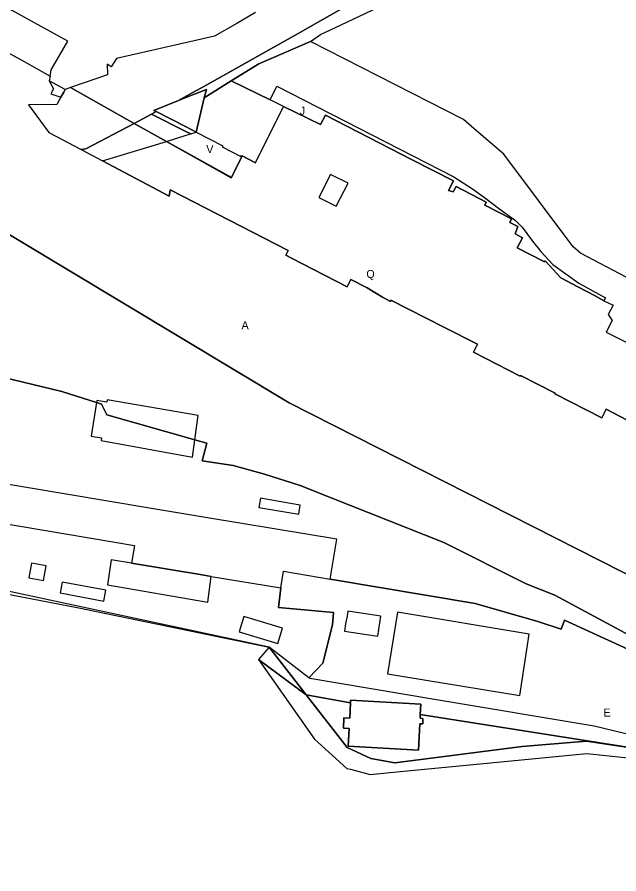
# Model space of a CAD drawing. Extents: x -749314 to -746497, y -1026537 to -1024935.
# Drawn here: x -748241.9 to -748054, y -1025476.4 to -1025208.8 of the extents above; entities that cross this region are included whole.
import ezdxf

# ---------------------------------------------------------------- set-up
doc = ezdxf.new("R2010")
doc.units = 0
for name, color, linetype in [('Default', 7, 'Continuous'), ('K_CD1', 7, 'Continuous'), ('K_DOSZDC1', 7, 'Continuous'), ('K_DOSZDC2', 7, 'Continuous'), ('K_JVL', 7, 'Continuous'), ('K_NH_JINE', 7, 'Continuous'), ('K_NH_SZDC', 7, 'Continuous'), ('K_SZDC1', 7, 'Continuous')]:
    doc.layers.add(name, color=color, linetype=linetype)

msp = doc.modelspace()

# ---------------------------------------------------------------- linework, layer by layer
at = {"layer": 'Default'}
for points in [[(-748047.05, -1025336.96), (-748057.96, -1025331.28), (-748059.35, -1025333.96), (-748073.97, -1025326.48), (-748073.86, -1025326.25), (-748084.73, -1025320.67), (-748084.85, -1025320.91), (-748099.36, -1025313.46), (-748098.09, -1025310.95), (-748108.66, -1025305.58), (-748125.15, -1025297.21), (-748125.32, -1025297.55), (-748127.81, -1025296.27), (-748132.58, -1025293.32), (-748137.68, -1025290.68), (-748138.87, -1025292.99), (-748156.19, -1025284.07), (-748157.97, -1025283.15), (-748157.21, -1025281.68), (-748194.14, -1025262.74), (-748194.41, -1025264.64), (-748215.2, -1025253.69), (-748195.28, -1025247.56), (-748174.98, -1025258.87), (-748171.61, -1025252.1), (-748167.43, -1025254.25), (-748158.67, -1025236.69), (-748147.14, -1025242.33), (-748145.62, -1025239.37), (-748118.74, -1025253.2), (-748105.67, -1025259.88), (-748107.19, -1025262.97), (-748105.72, -1025263.31), (-748104.83, -1025261.7), (-748095.39, -1025266.54), (-748095.82, -1025267.46), (-748087.47, -1025271.78), (-748088.01, -1025272.87), (-748085.58, -1025274.12), (-748086.39, -1025276.47), (-748084.11, -1025277.67), (-748085.71, -1025280.8), (-748077.2, -1025285.17), (-748077.04, -1025284.87), (-748072.07, -1025290.19), (-748066.78, -1025293.01), (-748061.42, -1025295.86), (-748058.64, -1025297.34), (-748055.78, -1025298.74), (-748057.27, -1025301.64), (-748056.1, -1025303.49), (-748057.97, -1025307.14), (-748044.75, -1025313.87)], [(-748259.36, -1025267.68), (-748156.97, -1025329.23), (-748032.2, -1025392.56), (-747926.21, -1025446.35), (-747932.75, -1025461.36), (-747968.57, -1025444.62), (-748049.38, -1025402.52), (-748073.99, -1025389.35), (-748082.88, -1025385.8), (-748108.65, -1025372.85), (-748143.78, -1025358.9), (-748153.5, -1025355.12), (-748164.65, -1025351.55), (-748174.46, -1025348.85), (-748184.1, -1025347.37), (-748182.63, -1025341.82), (-748186.39, -1025340.76), (-748185.38, -1025333.16), (-748213.73, -1025328.27), (-748213.86, -1025329.03), (-748217.05, -1025328.49), (-748217.16, -1025329.19), (-748227.91, -1025325.68), (-748255.65, -1025319)]]:
    msp.add_lwpolyline(points, dxfattribs=at)
for points in [[(-748215.2, -1025253.69), (-748195.28, -1025247.56), (-748205.38, -1025241.98), (-748220.46, -1025249.92), (-748221.95, -1025250.14)], [(-748147.68, -1025265.09), (-748142.23, -1025267.82), (-748138.47, -1025260.65), (-748144.06, -1025257.93)], [(-748213.88, -1025332.98), (-748186.39, -1025340.76), (-748185.38, -1025333.16), (-748213.73, -1025328.27), (-748213.86, -1025329.03), (-748217.05, -1025328.49), (-748217.16, -1025329.19), (-748215.58, -1025329.71)]]:
    msp.add_lwpolyline(points, close=True, dxfattribs=at)
at = {"layer": 'K_CD1'}
for points in [[(-748158.67, -1025236.69), (-748162.9, -1025234.62), (-748160.77, -1025230.33), (-748105.48, -1025258.65), (-748099.72, -1025262.35), (-748095.91, -1025265.14), (-748091.18, -1025268.7), (-748086.21, -1025272.25), (-748084.15, -1025274.39), (-748080.92, -1025278.7), (-748078.38, -1025282.02), (-748074.55, -1025286.01), (-748066.52, -1025291.88), (-748058.19, -1025296.44), (-748058.64, -1025297.34), (-748061.42, -1025295.86), (-748066.78, -1025293.01), (-748072.07, -1025290.19), (-748077.04, -1025284.87), (-748077.2, -1025285.17), (-748085.71, -1025280.8), (-748084.11, -1025277.67), (-748086.39, -1025276.47), (-748085.58, -1025274.12), (-748088.01, -1025272.87), (-748087.47, -1025271.78), (-748095.82, -1025267.46), (-748095.39, -1025266.54), (-748104.83, -1025261.7), (-748105.72, -1025263.31), (-748107.19, -1025262.97), (-748105.67, -1025259.88), (-748118.74, -1025253.2), (-748145.62, -1025239.37), (-748147.14, -1025242.33)], [(-748195.28, -1025247.56), (-748189.07, -1025245.65), (-748187.64, -1025245.2), (-748186, -1025244.7), (-748177.69, -1025248.98), (-748177.82, -1025249.24), (-748172.01, -1025252.26), (-748171.87, -1025251.97), (-748167.43, -1025254.25), (-748171.61, -1025252.1), (-748174.98, -1025258.87)], [(-748215.58, -1025329.71), (-748217.16, -1025329.19), (-748218.75, -1025339.67), (-748215.57, -1025340.21), (-748215.7, -1025341.01), (-748187.13, -1025346.26), (-748186.39, -1025340.76), (-748213.88, -1025332.98)], [(-748157.01, -1025363.53), (-748153.96, -1025364.04), (-748153.48, -1025361.17), (-748156.55, -1025360.66), (-748165.92, -1025359.08), (-748166.4, -1025361.95)], [(-748157.01, -1025363.53), (-748153.96, -1025364.04), (-748153.48, -1025361.17), (-748156.55, -1025360.66), (-748165.92, -1025359.08), (-748166.4, -1025361.95)], [(-748238.29, -1025383.92), (-748233.65, -1025384.77), (-748232.86, -1025380.17), (-748237.44, -1025379.33)], [(-748238.29, -1025383.92), (-748233.65, -1025384.77), (-748232.86, -1025380.17), (-748237.44, -1025379.33)], [(-748212.49, -1025378.32), (-748213.7, -1025386.14), (-748182.32, -1025391.5), (-748181.29, -1025383.46), (-748184.72, -1025382.89), (-748206.13, -1025379.32)], [(-748214.8, -1025391.19), (-748214.17, -1025387.81), (-748227.82, -1025385.26), (-748228.46, -1025388.65)], [(-748214.8, -1025391.19), (-748214.17, -1025387.81), (-748227.82, -1025385.26), (-748228.46, -1025388.65)], [(-748129.27, -1025402.17), (-748128.31, -1025395.86), (-748138.62, -1025394.29), (-748138.84, -1025395.74), (-748139.31, -1025398.31), (-748139.7, -1025400.56)], [(-748129.27, -1025402.17), (-748128.31, -1025395.86), (-748138.62, -1025394.29), (-748138.84, -1025395.74), (-748139.31, -1025398.31), (-748139.7, -1025400.56)], [(-748126.23, -1025413.91), (-748084.94, -1025420.71), (-748081.97, -1025401.56), (-748123.07, -1025394.62)], [(-748126.23, -1025413.91), (-748084.94, -1025420.71), (-748081.97, -1025401.56), (-748123.07, -1025394.62)], [(-748160.52, -1025404.42), (-748159.07, -1025399.67), (-748171.08, -1025396.01), (-748172.53, -1025400.76)], [(-748160.52, -1025404.42), (-748159.07, -1025399.67), (-748171.08, -1025396.01), (-748172.53, -1025400.76)], [(-748115.84, -1025423.38), (-748116.01, -1025426.66), (-748045.39, -1025437.77), (-748044.41, -1025437.98), (-748029.7, -1025440.89), (-748027.77, -1025441.28), (-748021.66, -1025442.5), (-748042.77, -1025434.89), (-748061.7, -1025430.24), (-748111.52, -1025421.94), (-748150.48, -1025415.41), (-748150.78, -1025415.18), (-748163.17, -1025405.57), (-748151.61, -1025420.44), (-748137.8, -1025422.95), (-748137.76, -1025422.13)], [(-748149.03, -1025434.28), (-748138.93, -1025443.46), (-748137.83, -1025443.74), (-748131.63, -1025445.33), (-748123.33, -1025444.53), (-748094.04, -1025441.72), (-748063.99, -1025438.84), (-748046.18, -1025440.63), (-748033.92, -1025443.55), (-748030.5, -1025444.36), (-748045.39, -1025437.77), (-748064.07, -1025434.97), (-748084.21, -1025436.6), (-748123.99, -1025441.67), (-748131.48, -1025440.38), (-748138.81, -1025436.89), (-748151.61, -1025420.44), (-748166.47, -1025409.42)], [(-748151.61, -1025420.44), (-748138.81, -1025436.89), (-748131.48, -1025440.38), (-748123.99, -1025441.67), (-748084.21, -1025436.6), (-748064.07, -1025434.97), (-748045.39, -1025437.77), (-748116.01, -1025426.66), (-748116.07, -1025427.79), (-748115.16, -1025427.84), (-748115.25, -1025429.55), (-748116.16, -1025429.5), (-748116.6, -1025437.71), (-748138.47, -1025436.54), (-748138.19, -1025430.94), (-748139.96, -1025430.85), (-748139.84, -1025427.7), (-748138.04, -1025427.78), (-748137.8, -1025422.95)], [(-748116.01, -1025426.66), (-748115.84, -1025423.38), (-748137.76, -1025422.13), (-748137.8, -1025422.95), (-748138.04, -1025427.78), (-748139.84, -1025427.7), (-748139.96, -1025430.85), (-748138.19, -1025430.94), (-748138.47, -1025436.54), (-748116.6, -1025437.71), (-748116.16, -1025429.5), (-748115.25, -1025429.55), (-748115.16, -1025427.84), (-748116.07, -1025427.79)]]:
    msp.add_lwpolyline(points, close=True, dxfattribs=at)
for points in [[(-748255.65, -1025319), (-748227.91, -1025325.68), (-748217.16, -1025329.19), (-748218.75, -1025339.67), (-748215.57, -1025340.21), (-748215.7, -1025341.01), (-748187.13, -1025346.26), (-748186.39, -1025340.76), (-748182.63, -1025341.82), (-748184.1, -1025347.37), (-748174.46, -1025348.85), (-748164.65, -1025351.55), (-748153.5, -1025355.12), (-748143.78, -1025358.9), (-748108.65, -1025372.85), (-748082.88, -1025385.8), (-748073.99, -1025389.35), (-748049.38, -1025402.52)], [(-748262.79, -1025364.15), (-748240.91, -1025367.81), (-748205.21, -1025373.78), (-748206.13, -1025379.32), (-748184.72, -1025382.89), (-748181.29, -1025383.46), (-748159.58, -1025387.09), (-748158.72, -1025381.87), (-748144.1, -1025384.29), (-748142.08, -1025371.86), (-748181.81, -1025365.24), (-748200.51, -1025362.12), (-748238.92, -1025355.73), (-748260.68, -1025352.1)], [(-748051.19, -1025406.25), (-748070.97, -1025397.13), (-748072.04, -1025399.99), (-748079.28, -1025397.58), (-748098.83, -1025391.94), (-748144.1, -1025384.29), (-748142.08, -1025371.86), (-748181.81, -1025365.24), (-748200.51, -1025362.12), (-748238.92, -1025355.73), (-748260.68, -1025352.1)], [(-748262.79, -1025364.15), (-748240.91, -1025367.81), (-748205.21, -1025373.78), (-748206.13, -1025379.32), (-748212.49, -1025378.32), (-748213.7, -1025386.14), (-748182.32, -1025391.5), (-748181.29, -1025383.46), (-748159.58, -1025387.09), (-748160.27, -1025393.17), (-748143.06, -1025394.77), (-748143.38, -1025398.62), (-748146.47, -1025410.62), (-748150.78, -1025415.18), (-748163.17, -1025405.57), (-748276.99, -1025381.25)], [(-748042.77, -1025434.89), (-748061.7, -1025430.24), (-748111.52, -1025421.94), (-748150.48, -1025415.41), (-748150.78, -1025415.18), (-748146.47, -1025410.62), (-748143.38, -1025398.62), (-748143.06, -1025394.77), (-748160.27, -1025393.17), (-748159.58, -1025387.09), (-748158.72, -1025381.87), (-748144.1, -1025384.29), (-748098.83, -1025391.94), (-748079.28, -1025397.58), (-748072.04, -1025399.99), (-748070.97, -1025397.13), (-748051.19, -1025406.25)]]:
    msp.add_lwpolyline(points, dxfattribs=at)
at = {"layer": 'K_DOSZDC1'}
for points in [[(-748262.56, -1025210.09), (-748239.75, -1025222.62), (-748231.61, -1025227.23), (-748231.86, -1025228.71), (-748230.54, -1025231.15), (-748231.14, -1025232.26), (-748231.4, -1025232.74), (-748228.23, -1025233.79), (-748229.47, -1025236.01), (-748238.37, -1025236.18), (-748231.98, -1025244.85), (-748221.95, -1025250.14), (-748215.2, -1025253.69), (-748194.41, -1025264.64), (-748194.14, -1025262.74), (-748157.21, -1025281.68), (-748157.97, -1025283.15), (-748156.19, -1025284.07), (-748138.87, -1025292.99), (-748137.68, -1025290.68), (-748132.58, -1025293.32), (-748127.81, -1025296.27), (-748125.32, -1025297.55), (-748125.15, -1025297.21), (-748108.66, -1025305.58), (-748098.09, -1025310.95), (-748099.36, -1025313.46), (-748084.85, -1025320.91), (-748084.73, -1025320.67), (-748073.86, -1025326.25), (-748073.97, -1025326.48), (-748059.35, -1025333.96), (-748057.96, -1025331.28), (-748047.05, -1025336.96)], [(-747860, -1025524.32), (-747873.67, -1025507.89), (-747884.53, -1025501.19), (-747921.73, -1025471.52), (-747916.35, -1025474.07), (-747914.56, -1025470.67), (-747923.1, -1025465.87), (-747932.75, -1025461.36), (-747926.21, -1025446.35), (-748032.2, -1025392.56), (-748156.97, -1025329.23), (-748259.36, -1025267.68)]]:
    msp.add_lwpolyline(points, dxfattribs=at)
at = {"layer": 'K_DOSZDC2'}
msp.add_lwpolyline([(-748230.54, -1025231.15), (-748231.14, -1025232.26), (-748231.4, -1025232.74), (-748228.23, -1025233.79), (-748227.35, -1025232.19), (-748226.86, -1025231.35), (-748231.86, -1025228.71)], close=True, dxfattribs=at)
at = {"layer": 'K_JVL'}
for points in [[(-748166.38, -1025223.3), (-748150.27, -1025216.4), (-748147.11, -1025214.17), (-748142.45, -1025211.97), (-748127.28, -1025204.83), (-748106.43, -1025195.73), (-748086.14, -1025190.3), (-748057.32, -1025175.84), (-748064.36, -1025177.27), (-748073.04, -1025179.04), (-748088.14, -1025182.11), (-748090.11, -1025177.34), (-748154.1, -1025213.87), (-748184.33, -1025230.86), (-748187.2, -1025232.44), (-748191.46, -1025234.78), (-748187.32, -1025233.13), (-748182.81, -1025231.33), (-748183.44, -1025233.95), (-748175.01, -1025228.69)], [(-748231.61, -1025227.23), (-748231.28, -1025225.26), (-748226.09, -1025216.29), (-748236.47, -1025210.53), (-748253.59, -1025201.03), (-748256.36, -1025199.44), (-748260.46, -1025197.09), (-748260.18, -1025196.6), (-748275.28, -1025188.56), (-748280.8, -1025185.62), (-748280.97, -1025183.96), (-748292.24, -1025179.16), (-748297.03, -1025190.29), (-748292.38, -1025193.05), (-748280.52, -1025200.07), (-748262.56, -1025210.09), (-748239.75, -1025222.62)], [(-748177.69, -1025248.98), (-748177.82, -1025249.24), (-748172.01, -1025252.26), (-748171.87, -1025251.97), (-748167.43, -1025254.25), (-748158.67, -1025236.69), (-748162.9, -1025234.62), (-748175.01, -1025228.69), (-748183.44, -1025233.95), (-748186, -1025244.7)], [(-748186, -1025244.7), (-748183.44, -1025233.95), (-748182.81, -1025231.33), (-748187.32, -1025233.13), (-748191.46, -1025234.78), (-748199.25, -1025237.88), (-748198.47, -1025238.28), (-748189.15, -1025243.08)], [(-748195.28, -1025247.56), (-748189.07, -1025245.65), (-748187.64, -1025245.2), (-748189.17, -1025244.44), (-748199.94, -1025239.12), (-748205.31, -1025241.94), (-748205.38, -1025241.98)], [(-748186, -1025244.7), (-748189.15, -1025243.08), (-748198.47, -1025238.28), (-748199.94, -1025239.12), (-748189.17, -1025244.44), (-748187.64, -1025245.2)], [(-748138.47, -1025260.65), (-748144.06, -1025257.93), (-748147.68, -1025265.09), (-748142.23, -1025267.82)], [(-748166.47, -1025409.42), (-748151.61, -1025420.44), (-748163.17, -1025405.57)]]:
    msp.add_lwpolyline(points, close=True, dxfattribs=at)
for points in [[(-748167.42, -1025207.34), (-748173.32, -1025210.72), (-748180.24, -1025214.69), (-748184.36, -1025215.63), (-748210.85, -1025221.66), (-748212.48, -1025224.27), (-748213.78, -1025223.47), (-748213.72, -1025226.77), (-748225.26, -1025230.79), (-748215.62, -1025236.18), (-748205.31, -1025241.94), (-748199.94, -1025239.12), (-748198.47, -1025238.28), (-748199.25, -1025237.88), (-748191.46, -1025234.78), (-748187.2, -1025232.44), (-748184.33, -1025230.86), (-748154.1, -1025213.87), (-748090.11, -1025177.34)], [(-748049.7, -1025291.02), (-748065.92, -1025282.45), (-748068.25, -1025280.47), (-748089.93, -1025251.55), (-748099.13, -1025243.69), (-748102.55, -1025240.77), (-748150.27, -1025216.4), (-748166.38, -1025223.3), (-748175.01, -1025228.69), (-748162.9, -1025234.62), (-748160.77, -1025230.33), (-748105.48, -1025258.65), (-748099.72, -1025262.35), (-748095.91, -1025265.14), (-748091.18, -1025268.7), (-748086.21, -1025272.25), (-748084.15, -1025274.39), (-748080.92, -1025278.7), (-748078.38, -1025282.02), (-748074.55, -1025286.01), (-748066.52, -1025291.88), (-748058.19, -1025296.44), (-748058.64, -1025297.34), (-748055.78, -1025298.74), (-748057.27, -1025301.64), (-748056.1, -1025303.49), (-748057.97, -1025307.14), (-748044.75, -1025313.87)], [(-748256.79, -1025386.73), (-748223.14, -1025393.21), (-748163.17, -1025405.57), (-748276.99, -1025381.25)]]:
    msp.add_lwpolyline(points, dxfattribs=at)
at = {"layer": 'K_NH_JINE'}
msp.add_lwpolyline([(-748158.67, -1025236.69), (-748147.14, -1025242.33), (-748145.62, -1025239.37), (-748118.74, -1025253.2), (-748105.67, -1025259.88), (-748107.19, -1025262.97), (-748105.72, -1025263.31), (-748104.83, -1025261.7), (-748095.39, -1025266.54), (-748095.82, -1025267.46), (-748087.47, -1025271.78), (-748088.01, -1025272.87), (-748085.58, -1025274.12), (-748086.39, -1025276.47), (-748084.11, -1025277.67), (-748085.71, -1025280.8), (-748077.2, -1025285.17), (-748077.04, -1025284.87), (-748072.07, -1025290.19), (-748066.78, -1025293.01), (-748061.42, -1025295.86), (-748058.64, -1025297.34)], dxfattribs=at)
at = {"layer": 'K_NH_SZDC'}
msp.add_lwpolyline([(-748195.28, -1025247.56), (-748175.02, -1025258.94), (-748171.61, -1025252.1)], dxfattribs=at)
at = {"layer": 'K_SZDC1'}
msp.add_lwpolyline([(-748226.86, -1025231.35), (-748227.35, -1025232.19), (-748228.23, -1025233.79), (-748229.47, -1025236.01), (-748238.37, -1025236.18), (-748231.98, -1025244.85), (-748221.95, -1025250.14), (-748220.46, -1025249.92), (-748205.38, -1025241.98), (-748205.31, -1025241.94), (-748215.62, -1025236.18), (-748225.26, -1025230.79)], close=True, dxfattribs=at)

# ---------------------------------------------------------------- texts
for s, p in [('J', (-748153.62, -1025239.25)), ('V', (-748182.82, -1025251.25)), ('Q', (-748132.83, -1025290.25)), ('A', (-748171.82, -1025306.25)), ('E', (-748058.77, -1025427.25))]:
    msp.add_text(s, height=2.5).set_placement(p)

doc.saveas('drawing.dxf')
